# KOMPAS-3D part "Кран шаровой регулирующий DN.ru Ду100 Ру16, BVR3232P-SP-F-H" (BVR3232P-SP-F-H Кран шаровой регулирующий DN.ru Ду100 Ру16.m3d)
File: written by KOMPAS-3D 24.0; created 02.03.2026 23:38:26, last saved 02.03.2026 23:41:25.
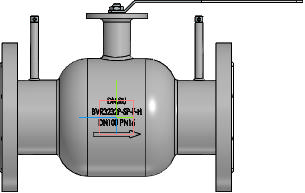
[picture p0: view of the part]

Document properties: Автор: Максим; Полное имя файла: BVR3232P-SP-F-H - Кран шаровой регулирующий DN.ru  Ду100 Ру16.cdw

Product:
- Body: Тело 1  | qty 1
    Масса: 33.551312
- Part/product: Кран шаровой регулирующий DN.ru Ду100 Ру16  | designation BVR3232P-SP-F-H
    Масса: 21.1
    Раздел спецификации: Прочие изделия
    Форматы листов документа: A3
    Примечание: D160-69425

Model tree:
1. Операция без истории:1

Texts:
  BVR3232P-SP-F-H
